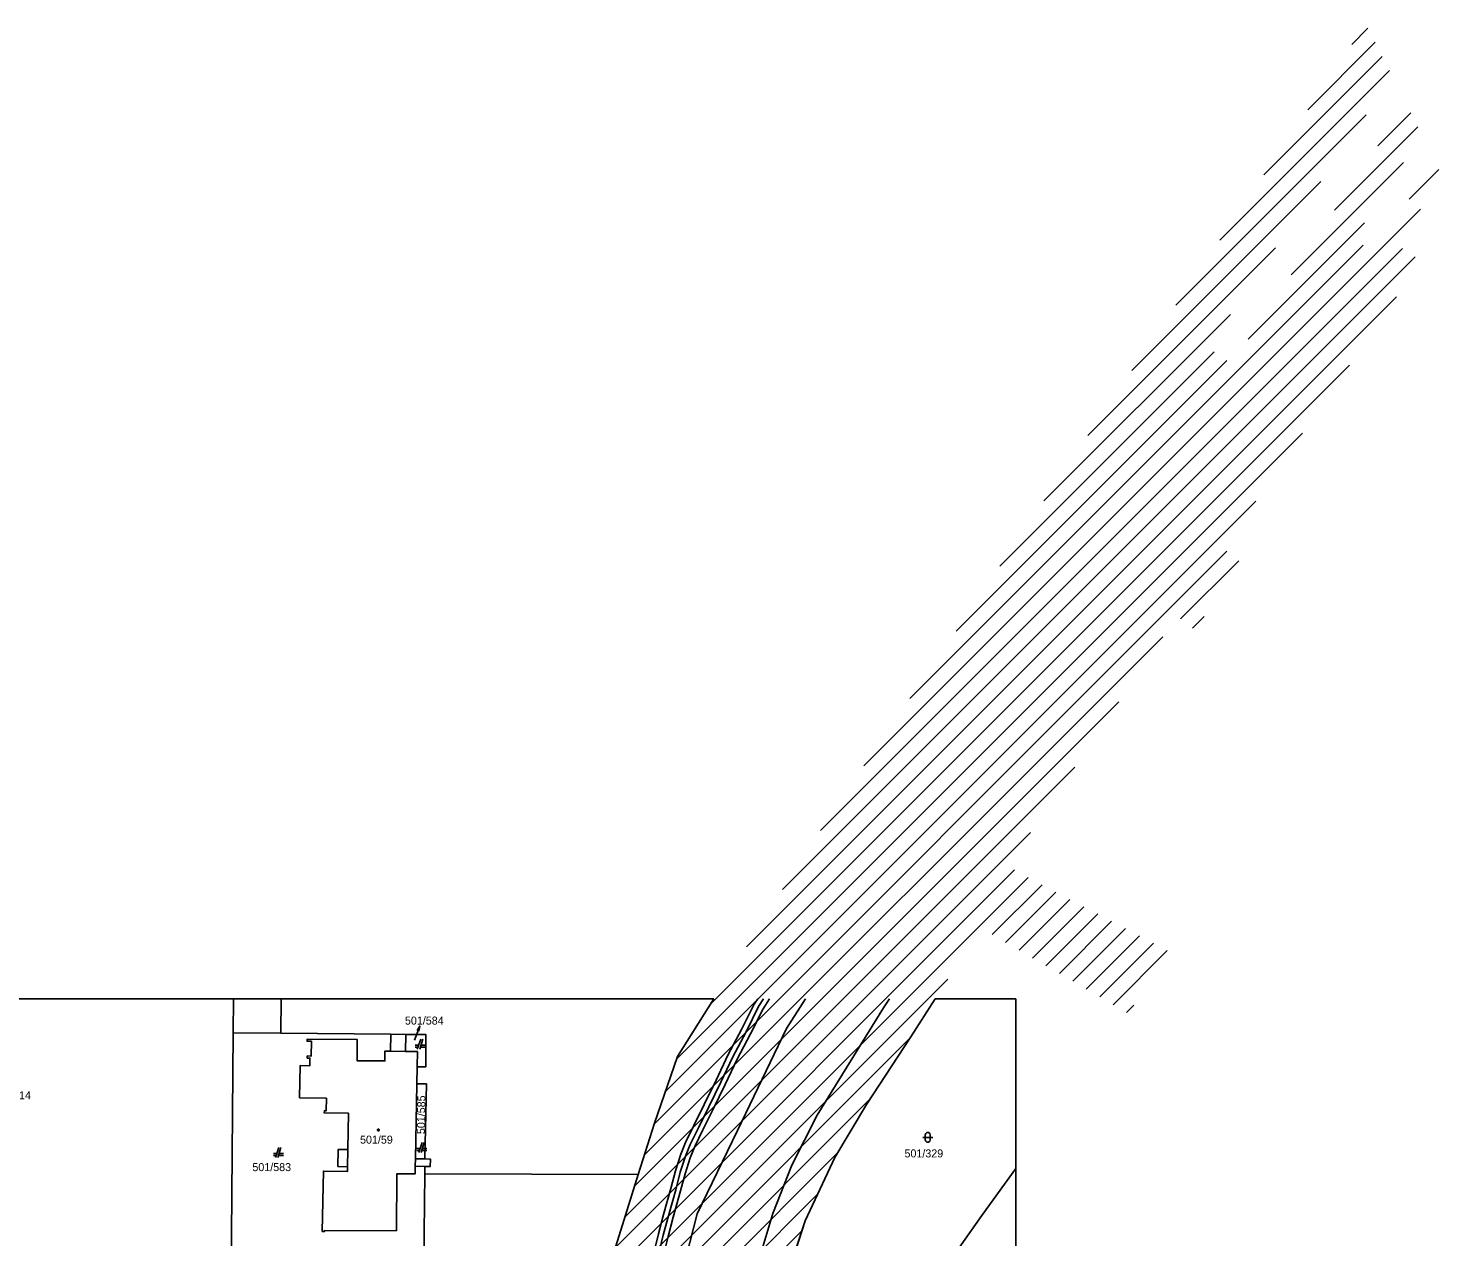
# Model space of a CAD drawing. Extents: x -264309 to -263505, y -1242443 to -1241763.
# Drawn here: x -263786.7 to -263504.8, y -1242004.6 to -1241763 of the extents above; entities that cross this region are included whole.
import ezdxf

# ---------------------------------------------------------------- set-up
doc = ezdxf.new("R2010")
doc.units = 0
for name, color, linetype in [('KN_2019_08_16', 7, 'Continuous'), ('KN_2019_08_16_KLADPAR', 7, 'Continuous'), ('KN_2019_08_16_ZAPPAR', 7, 'Continuous'), ('SRAFY_PARCELY', 7, 'Continuous')]:
    doc.layers.add(name, color=color, linetype=linetype)

msp = doc.modelspace()

# ---------------------------------------------------------------- linework, layer by layer
at = {"layer": 'KN_2019_08_16'}
for points in [[(-263661.36, -1242010.65), (-263659.8, -1242004.23), (-263658.77, -1242000.36), (-263657.3, -1241995.14), (-263656.4, -1241991.67), (-263655.36, -1241988.42), (-263654.4, -1241986.12), (-263652.77, -1241982.77), (-263650.68, -1241978.58), (-263648.3, -1241973.67), (-263645.91, -1241968.57), (-263643.24, -1241963.56), (-263640.72, -1241958.52), (-263639.73, -1241956.96)], [(-263638.54, -1241956.96), (-263639.85, -1241959.01), (-263642.35, -1241964.02), (-263645.02, -1241969.02), (-263647.4, -1241974.1), (-263649.78, -1241979.02), (-263651.87, -1241983.21), (-263653.49, -1241986.53), (-263654.42, -1241988.77), (-263655.44, -1241991.95), (-263656.33, -1241995.4), (-263657.81, -1242000.62), (-263658.83, -1242004.48), (-263660.39, -1242010.9)], [(-263649.2, -1241973.24), (-263646.8, -1241968.12), (-263644.13, -1241963.1), (-263641.59, -1241958.03), (-263640.91, -1241956.96)], [(-263662.33, -1242010.4), (-263660.77, -1242003.98), (-263659.73, -1242000.1), (-263658.27, -1241994.88), (-263657.36, -1241991.39), (-263656.3, -1241988.07), (-263655.31, -1241985.71), (-263653.67, -1241982.33), (-263651.58, -1241978.14), (-263649.2, -1241973.24)]]:
    msp.add_lwpolyline(points, dxfattribs=at)
at = {"layer": 'KN_2019_08_16_KLADPAR'}
for p, q in [((-263830.29, -1241956.96), (-263745.67, -1241956.96)), ((-263745.67, -1241956.96), (-263745.73, -1241963.8)), ((-263745.73, -1241963.8), (-263745.67, -1241956.96)), ((-263745.67, -1241956.96), (-263736.17, -1241956.96)), ((-263736.23, -1241963.88), (-263736.17, -1241956.96)), ((-263736.17, -1241956.96), (-263736.23, -1241963.88)), ((-263736.17, -1241956.96), (-263649.68, -1241956.96)), ((-263649.68, -1241956.96), (-263656.95, -1241968.51)), ((-263610.27, -1241964.57), (-263605.42, -1241956.96)), ((-263605.42, -1241956.96), (-263589.31, -1241956.96)), ((-263589.31, -1241956.96), (-263589.31, -1241990.93)), ((-263708.99, -1241963.31), (-263708.47, -1241962.44)), ((-263745.73, -1241963.8), (-263746.09, -1242004.16)), ((-263736.23, -1241963.88), (-263745.73, -1241963.8)), ((-263714.25, -1241964.08), (-263736.23, -1241963.88)), ((-263711.27, -1241964.1), (-263714.25, -1241964.08)), ((-263707.23, -1241964.13), (-263711.27, -1241964.1)), ((-263708.27, -1241965.03), (-263708.97, -1241967.03)), ((-263708.47, -1241967.03), (-263707.87, -1241965.03)), ((-263707.28, -1241970.59), (-263707.23, -1241964.13)), ((-263619.17, -1241978.14), (-263610.27, -1241964.57)), ((-263708.69, -1241966.23), (-263709.37, -1241966.23)), ((-263709.37, -1241966.63), (-263708.83, -1241966.63)), ((-263708.35, -1241966.63), (-263707.37, -1241966.63)), ((-263707.37, -1241966.23), (-263708.23, -1241966.23)), ((-263709.05, -1241973.99), (-263708.99, -1241970.58)), ((-263708.99, -1241970.58), (-263707.28, -1241970.59)), ((-263656.95, -1241968.51), (-263661.56, -1241981.85)), ((-263707.13, -1241974), (-263709.05, -1241973.99)), ((-263707.42, -1241989), (-263707.13, -1241974)), ((-263625.48, -1241988.68), (-263619.17, -1241978.14)), ((-263661.56, -1241981.85), (-263664.79, -1241992.08)), ((-263737.03, -1241987.88), (-263737.71, -1241987.88)), ((-263736.61, -1241986.68), (-263737.31, -1241988.68)), ((-263736.81, -1241988.68), (-263736.21, -1241986.68)), ((-263735.71, -1241987.88), (-263736.57, -1241987.88)), ((-263708.38, -1241986.9), (-263709.06, -1241986.9)), ((-263709.06, -1241987.3), (-263708.52, -1241987.3)), ((-263707.96, -1241985.7), (-263708.66, -1241987.7)), ((-263708.16, -1241987.7), (-263707.56, -1241985.7)), ((-263708.04, -1241987.3), (-263707.06, -1241987.3)), ((-263707.06, -1241986.9), (-263707.92, -1241986.9)), ((-263737.71, -1241988.28), (-263737.17, -1241988.28)), ((-263736.69, -1241988.28), (-263735.71, -1241988.28)), ((-263707.47, -1241991.99), (-263707.45, -1241990.49)), ((-263707.45, -1241990.49), (-263706.36, -1241990.5)), ((-263706.34, -1241989.01), (-263707.42, -1241989)), ((-263706.36, -1241990.5), (-263706.34, -1241989.01)), ((-263631.39, -1242001.36), (-263625.48, -1241988.68)), ((-263589.31, -1241990.93), (-263596.1, -1242000.33)), ((-263596.1, -1242000.33), (-263589.31, -1241990.93)), ((-263589.31, -1241990.93), (-263589.31, -1242014.51)), ((-263664.79, -1241992.08), (-263707.47, -1241991.99)), ((-263635.33, -1242013.32), (-263631.39, -1242001.36)), ((-263596.1, -1242000.33), (-263606.1, -1242014.38)), ((-263606.1, -1242014.38), (-263596.1, -1242000.33)), ((-263746.09, -1242004.16), (-263746.07, -1242009.46))]:
    msp.add_line(p, q, dxfattribs=at)
for points in [[(-263681.58, -1242045.97), (-263667.36, -1242000.21), (-263664.79, -1241992.08), (-263661.56, -1241981.85), (-263656.95, -1241968.51), (-263649.68, -1241956.96)], [(-263605.42, -1241956.96), (-263610.27, -1241964.57), (-263619.17, -1241978.14), (-263625.48, -1241988.68), (-263631.39, -1242001.36), (-263635.33, -1242013.32)], [(-263709.48, -1241965.26), (-263708.47, -1241962.44), (-263708.62, -1241963.45)], [(-263746.07, -1242009.46), (-263746.09, -1242004.16), (-263745.73, -1241963.8), (-263736.23, -1241963.88), (-263714.25, -1241964.08), (-263714.28, -1241967.46), (-263715.43, -1241967.45), (-263715.44, -1241969.41), (-263720.98, -1241969.37), (-263720.95, -1241965.14), (-263731, -1241965.06), (-263731, -1241965.47), (-263730.13, -1241965.48), (-263730.16, -1241968.42), (-263730.96, -1241968.41), (-263730.96, -1241968.84), (-263730.41, -1241968.84), (-263730.42, -1241970.36), (-263732.39, -1241970.35), (-263732.5, -1241976.76), (-263727.11, -1241976.85), (-263727.16, -1241979.35), (-263727.53, -1241979.35), (-263727.54, -1241979.78), (-263722.73, -1241979.86), (-263722.85, -1241987.13), (-263724.76, -1241987.09), (-263724.82, -1241990.54), (-263722.92, -1241990.58), (-263722.93, -1241991.52), (-263727.73, -1241991.44), (-263727.94, -1242003.49), (-263727.49, -1242003.49), (-263727.49, -1242003.27), (-263713.13, -1242003.34), (-263713.02, -1241991.95), (-263709.38, -1241991.99), (-263709.36, -1241990.47), (-263707.45, -1241990.49), (-263707.47, -1241991.99), (-263707.65, -1242009.54)], [(-263607.93, -1241984.68), (-263606.66, -1241984.68), (-263605.93, -1241984.68)]]:
    msp.add_lwpolyline(points, dxfattribs=at)
for points in [[(-263731, -1241965.06), (-263720.95, -1241965.14), (-263720.98, -1241969.37), (-263715.44, -1241969.41), (-263715.43, -1241967.45), (-263714.28, -1241967.46), (-263714.25, -1241964.08), (-263711.27, -1241964.1), (-263711.3, -1241967.5), (-263708.93, -1241967.52), (-263708.99, -1241970.58), (-263709.05, -1241973.99), (-263709.34, -1241988.97), (-263707.42, -1241989), (-263706.34, -1241989.01), (-263706.36, -1241990.5), (-263707.45, -1241990.49), (-263709.36, -1241990.47), (-263709.38, -1241991.99), (-263713.02, -1241991.95), (-263713.13, -1242003.34), (-263727.49, -1242003.27), (-263727.49, -1242003.49), (-263727.94, -1242003.49), (-263727.73, -1241991.44), (-263722.93, -1241991.52), (-263722.92, -1241990.58), (-263724.82, -1241990.54), (-263724.76, -1241987.09), (-263722.85, -1241987.13), (-263722.73, -1241979.86), (-263727.54, -1241979.78), (-263727.53, -1241979.35), (-263727.16, -1241979.35), (-263727.11, -1241976.85), (-263732.5, -1241976.76), (-263732.39, -1241970.35), (-263730.42, -1241970.36), (-263730.41, -1241968.84), (-263730.96, -1241968.84), (-263730.96, -1241968.41), (-263730.16, -1241968.42), (-263730.13, -1241965.48), (-263731, -1241965.47)], [(-263711.27, -1241964.1), (-263707.23, -1241964.13), (-263707.28, -1241970.59), (-263708.99, -1241970.58), (-263708.93, -1241967.52), (-263711.3, -1241967.5)], [(-263709.05, -1241973.99), (-263707.13, -1241974), (-263707.42, -1241989), (-263709.34, -1241988.97)], [(-263716.64, -1241983.07), (-263716.55, -1241983.22), (-263716.64, -1241983.37), (-263716.82, -1241983.37), (-263716.91, -1241983.22), (-263716.82, -1241983.07)], [(-263607.43, -1241984.18), (-263607.33, -1241983.89), (-263607.08, -1241983.71), (-263606.77, -1241983.71), (-263606.52, -1241983.89), (-263606.42, -1241984.18), (-263606.42, -1241985.18), (-263606.52, -1241985.47), (-263606.77, -1241985.65), (-263607.08, -1241985.65), (-263607.33, -1241985.47), (-263607.43, -1241985.18)], [(-263707.47, -1241991.99), (-263664.79, -1241992.08), (-263667.36, -1242000.21), (-263681.58, -1242045.97), (-263742.18, -1242041.73), (-263746.1, -1242041.26), (-263746.03, -1242018.11), (-263707.74, -1242018.19), (-263707.65, -1242009.54)]]:
    msp.add_lwpolyline(points, close=True, dxfattribs=at)
at = {"layer": 'KN_2019_08_16_ZAPPAR'}
for p, q in [((-263615.79, -1241958.8), (-263629.01, -1241980.26)), ((-263714.28, -1241967.46), (-263711.3, -1241967.5)), ((-263644.96, -1241983.33), (-263653.04, -1242000)), ((-263722.92, -1241990.58), (-263722.85, -1241987.13)), ((-263709.34, -1241988.97), (-263709.36, -1241990.47))]:
    msp.add_line(p, q, dxfattribs=at)
for points in [[(-263631.36, -1241956.96), (-263635.14, -1241962.94), (-263644.96, -1241983.33)], [(-263614.55, -1241956.96), (-263615.79, -1241958.8)], [(-263629.01, -1241980.26), (-263634.11, -1241990.21), (-263637.9, -1241999.88), (-263640.1, -1242007.24), (-263642.22, -1242014.92), (-263643.99, -1242021.55), (-263651.18, -1242056.5)], [(-263653.04, -1242000), (-263661.96, -1242034.89), (-263663.39, -1242040.38)]]:
    msp.add_lwpolyline(points, dxfattribs=at)
at = {"layer": 'SRAFY_PARCELY'}
for p, q in [((-263522.17, -1241766.22), (-263518.92, -1241762.97)), ((-263530.96, -1241779.25), (-263517.49, -1241765.78)), ((-263539.74, -1241792.28), (-263516.06, -1241768.59)), ((-263548.53, -1241805.31), (-263514.63, -1241771.41)), ((-263557.32, -1241818.34), (-263519.28, -1241780.3)), ((-263516.96, -1241786.46), (-263510.36, -1241779.87)), ((-263525.6, -1241799.35), (-263508.97, -1241782.71)), ((-263534.25, -1241812.24), (-263511.81, -1241789.8)), ((-263566.11, -1241831.38), (-263528.33, -1241793.59)), ((-263510.67, -1241797.15), (-263504.77, -1241791.24)), ((-263619.71, -1241910.43), (-263508.44, -1241799.16)), ((-263542.9, -1241825.13), (-263519.63, -1241801.87)), ((-263628.35, -1241923.31), (-263512.01, -1241806.97)), ((-263610.5, -1241896.98), (-263519.87, -1241806.34)), ((-263574.9, -1241844.41), (-263537.38, -1241806.89)), ((-263635.95, -1241935.15), (-263509.5, -1241808.7)), ((-263643.16, -1241946.61), (-263513.25, -1241816.69)), ((-263583.69, -1241857.44), (-263546.43, -1241820.18)), ((-263601.27, -1241883.5), (-263547.16, -1241829.39)), ((-263592.48, -1241870.47), (-263549.69, -1241827.68)), ((-263650.37, -1241958.06), (-263522.62, -1241830.31)), ((-263657.15, -1241969.08), (-263531.98, -1241843.91)), ((-263659.39, -1241975.56), (-263541.34, -1241857.51)), ((-263661.62, -1241982.04), (-263547.12, -1241867.53)), ((-263556.37, -1241881.03), (-263544.77, -1241869.43)), ((-263554.02, -1241882.92), (-263551.65, -1241880.55)), ((-263663.58, -1241988.24), (-263559.96, -1241884.62)), ((-263665.54, -1241994.44), (-263568.75, -1241897.65)), ((-263667.49, -1242000.64), (-263577.55, -1241910.7)), ((-263669.41, -1242006.79), (-263586.35, -1241923.74)), ((-263671.32, -1242012.95), (-263589.58, -1241931.21)), ((-263673.23, -1242019.1), (-263586.87, -1241932.74)), ((-263594.04, -1241944.16), (-263584.08, -1241934.2)), ((-263591.36, -1241945.71), (-263581.3, -1241935.65)), ((-263588.67, -1241947.27), (-263578.51, -1241937.11)), ((-263585.98, -1241948.83), (-263575.73, -1241938.57)), ((-263583.29, -1241950.38), (-263572.95, -1241940.03)), ((-263580.61, -1241951.94), (-263570.16, -1241941.49)), ((-263577.92, -1241953.49), (-263567.38, -1241942.95)), ((-263575.23, -1241955.05), (-263564.59, -1241944.41)), ((-263572.55, -1241956.6), (-263561.81, -1241945.87)), ((-263569.86, -1241958.16), (-263559.03, -1241947.33)), ((-263675.14, -1242025.26), (-263602.92, -1241953.03)), ((-263567.17, -1241959.71), (-263565.73, -1241958.27)), ((-263677.06, -1242031.42), (-263610.38, -1241964.74)), ((-263678.97, -1242037.57), (-263618.47, -1241977.07)), ((-263680.88, -1242043.73), (-263624.95, -1241987.79)), ((-263683.5, -1242050.58), (-263628.87, -1241995.96)), ((-263682.84, -1242054.17), (-263632.06, -1242003.39))]:
    msp.add_line(p, q, dxfattribs=at)

# ---------------------------------------------------------------- texts
at = {"layer": 'KN_2019_08_16_KLADPAR'}
for s, p in [('501/584', (-263711.42, -1241962.14)), ('501/614', (-263793.91, -1241977.07)), ('501/59', (-263720.4, -1241985.94)), ('501/329', (-263611.57, -1241988.69)), ('501/583', (-263741.92, -1241991.43))]:
    msp.add_text(s, height=1.6, dxfattribs=at).set_placement(p)
msp.add_text('501/585', height=1.6, rotation=89.2095, dxfattribs=at).set_placement((-263707.44, -1241984.04))

doc.saveas('drawing.dxf')
